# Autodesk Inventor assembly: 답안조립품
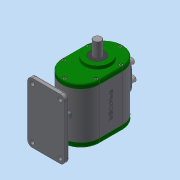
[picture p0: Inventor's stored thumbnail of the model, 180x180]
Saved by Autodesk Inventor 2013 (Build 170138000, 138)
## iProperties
Created: 2018-10
Part Number: 답안조립품
Document SubType Name: Assembly
Designer: Administrator
Author: Administrator
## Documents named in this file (15)
- C:\Users\Administrator\Desktop\381007V1011\답안조립품.iam
- C:\Users\Administrator\Desktop\381007V1011\본체.ipt
- C:\Users\Administrator\Desktop\381007V1011\가변스프링.ipt
- C:\Users\Administrator\Desktop\381007V1011\가변스프링2.ipt
- C:\Users\Administrator\Desktop\381007V1011\뒤커버.ipt
- C:\Users\Administrator\Desktop\381007V1011\메인축.ipt
- C:\Users\Administrator\Desktop\381007V1011\베어링 608.ipt
- C:\Users\Administrator\Desktop\381007V1011\베어링 6003.ipt
- C:\Users\Administrator\Desktop\381007V1011\볼트 M4.ipt
- C:\Users\Administrator\Desktop\381007V1011\부시.ipt
- C:\Users\Administrator\Desktop\381007V1011\서브축.ipt
- C:\Users\Administrator\Desktop\381007V1011\슬라이더.ipt
- C:\Users\Administrator\Desktop\381007V1011\앞커버.ipt
- C:\Users\Administrator\Desktop\381007V1011\오일실 8 22 7.ipt
- C:\Users\Administrator\Desktop\381007V1011\오일실 17 32 8.ipt
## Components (2 placed, 2 different names)
1. 가변스프링:1
2. 가변스프링2:1
